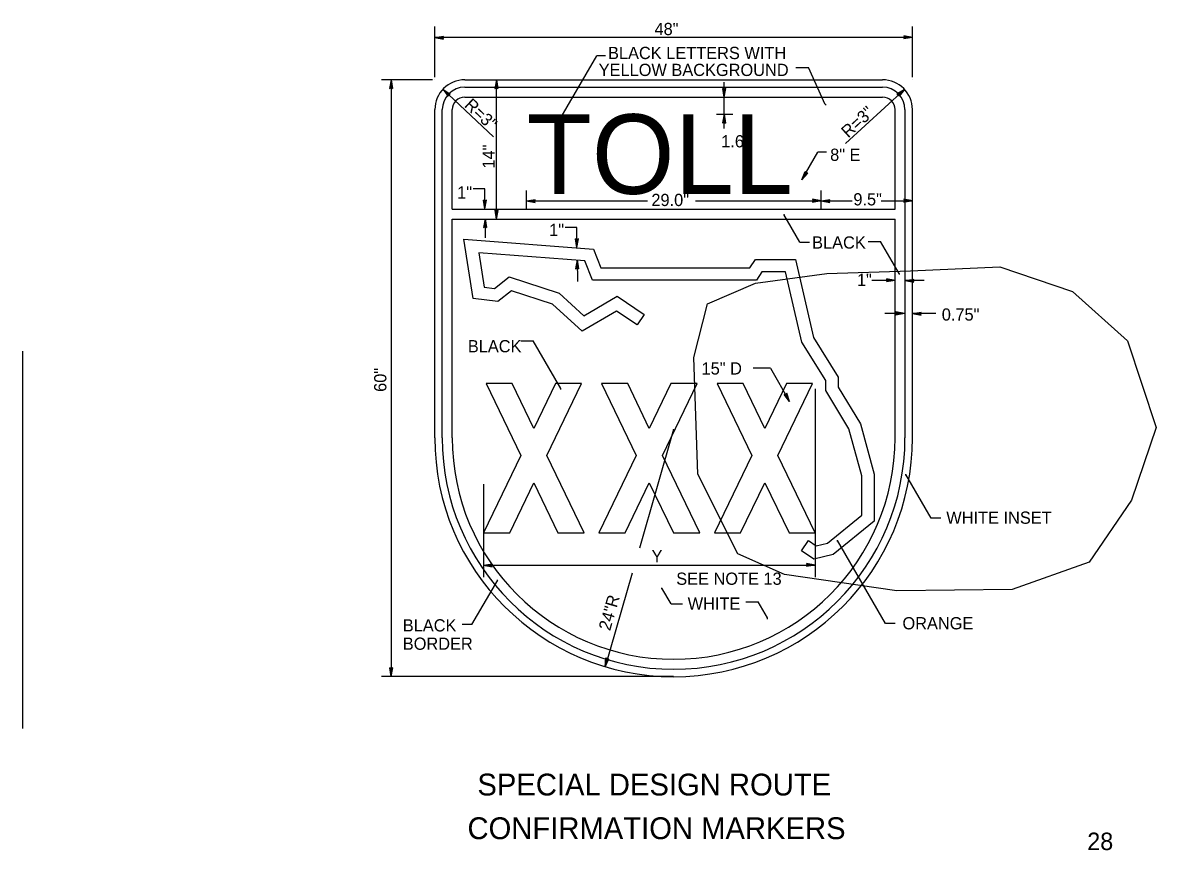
# Model space of a CAD drawing. Extents: x 51788 to 52424, y 9835 to 10249.
# Drawn here: x 52164.7 to 52424.2, y 9845.3 to 10034.8 of the extents above; entities that cross this region are included whole.
import ezdxf

# ---------------------------------------------------------------- set-up
doc = ezdxf.new("R2010")
doc.units = 0
for name, color, linetype in [('DimLines_dp', 7, 'Continuous'), ('GSColorFill', 7, 'Continuous'), ('GSDims', 7, 'Continuous'), ('SignPanel', 7, 'Continuous'), ('TextAlert', 7, 'Continuous'), ('TextMisc', 7, 'Continuous'), ('TextShtNo', 7, 'Continuous')]:
    doc.layers.add(name, color=color, linetype=linetype)

msp = doc.modelspace()

# ---------------------------------------------------------------- linework, layer by layer
at = {"layer": 'DimLines_dp'}
msp.add_line((52313.7, 9941.63), (52313.7, 9941.63), dxfattribs=at)
msp.add_line((52313.7, 9941.63), (52313.7, 9941.63), dxfattribs=at)
for radius in [0.0387, 0.0387, 0.0193]:
    msp.add_circle((52313.7, 9941.63), radius, dxfattribs=at)
at = {"layer": 'GSColorFill'}
for p, q in [((52270.76, 9952.16), (52278.69, 9935.69)), ((52276.75, 9952.16), (52270.76, 9952.16)), ((52270.76, 9952.16), (52278.69, 9935.69)), ((52276.75, 9952.16), (52270.76, 9952.16)), ((52281.69, 9941.91), (52276.75, 9952.16)), ((52281.69, 9941.91), (52276.75, 9952.16)), ((52286.63, 9952.16), (52281.69, 9941.91)), ((52286.63, 9952.16), (52281.69, 9941.91)), ((52284.69, 9935.69), (52292.63, 9952.16)), ((52284.69, 9935.69), (52292.63, 9952.16)), ((52292.63, 9952.16), (52286.63, 9952.16)), ((52292.63, 9952.16), (52286.63, 9952.16)), ((52297.2, 9952.16), (52305.13, 9935.69)), ((52303.19, 9952.16), (52297.2, 9952.16)), ((52297.2, 9952.16), (52305.13, 9935.69)), ((52303.19, 9952.16), (52297.2, 9952.16)), ((52308.13, 9941.91), (52303.19, 9952.16)), ((52308.13, 9941.91), (52303.19, 9952.16)), ((52313.07, 9952.16), (52308.13, 9941.91)), ((52313.07, 9952.16), (52308.13, 9941.91)), ((52311.13, 9935.69), (52319.07, 9952.16)), ((52311.13, 9935.69), (52319.07, 9952.16)), ((52319.07, 9952.16), (52313.07, 9952.16)), ((52319.07, 9952.16), (52313.07, 9952.16)), ((52323.64, 9952.16), (52331.58, 9935.69)), ((52329.63, 9952.16), (52323.64, 9952.16)), ((52323.64, 9952.16), (52331.58, 9935.69)), ((52329.63, 9952.16), (52323.64, 9952.16)), ((52334.57, 9941.91), (52329.63, 9952.16)), ((52334.57, 9941.91), (52329.63, 9952.16)), ((52339.51, 9952.16), (52334.57, 9941.91)), ((52339.51, 9952.16), (52334.57, 9941.91)), ((52337.57, 9935.69), (52345.51, 9952.16)), ((52337.57, 9935.69), (52345.51, 9952.16)), ((52345.51, 9952.16), (52339.51, 9952.16)), ((52345.51, 9952.16), (52339.51, 9952.16)), ((52278.69, 9935.69), (52270.16, 9917.99)), ((52278.69, 9935.69), (52270.16, 9917.99)), ((52293.22, 9917.99), (52284.69, 9935.69)), ((52293.22, 9917.99), (52284.69, 9935.69)), ((52305.13, 9935.69), (52296.6, 9917.99)), ((52305.13, 9935.69), (52296.6, 9917.99)), ((52319.66, 9917.99), (52311.13, 9935.69)), ((52319.66, 9917.99), (52311.13, 9935.69)), ((52331.58, 9935.69), (52323.05, 9917.99)), ((52331.58, 9935.69), (52323.05, 9917.99)), ((52346.1, 9917.99), (52337.57, 9935.69)), ((52346.1, 9917.99), (52337.57, 9935.69)), ((52276.16, 9917.99), (52281.69, 9929.47)), ((52276.16, 9917.99), (52281.69, 9929.47)), ((52281.69, 9929.47), (52287.22, 9917.99)), ((52281.69, 9929.47), (52287.22, 9917.99)), ((52302.6, 9917.99), (52308.13, 9929.47)), ((52302.6, 9917.99), (52308.13, 9929.47)), ((52308.13, 9929.47), (52313.67, 9917.99)), ((52308.13, 9929.47), (52313.67, 9917.99)), ((52329.04, 9917.99), (52334.57, 9929.47)), ((52329.04, 9917.99), (52334.57, 9929.47)), ((52334.57, 9929.47), (52340.11, 9917.99)), ((52334.57, 9929.47), (52340.11, 9917.99)), ((52270.16, 9917.99), (52276.16, 9917.99)), ((52270.16, 9917.99), (52276.16, 9917.99)), ((52287.22, 9917.99), (52293.22, 9917.99)), ((52287.22, 9917.99), (52293.22, 9917.99)), ((52296.6, 9917.99), (52302.6, 9917.99)), ((52296.6, 9917.99), (52302.6, 9917.99)), ((52313.67, 9917.99), (52319.66, 9917.99)), ((52313.67, 9917.99), (52319.66, 9917.99)), ((52323.05, 9917.99), (52329.04, 9917.99)), ((52323.05, 9917.99), (52329.04, 9917.99)), ((52340.11, 9917.99), (52346.1, 9917.99)), ((52340.11, 9917.99), (52346.1, 9917.99))]:
    msp.add_line(p, q, dxfattribs=at)
for points in [[(52270.76, 9952.16), (52278.69, 9935.69), (52270.16, 9917.99), (52276.16, 9917.99), (52281.69, 9929.47), (52287.22, 9917.99), (52293.22, 9917.99), (52284.69, 9935.69), (52292.63, 9952.16), (52286.63, 9952.16), (52281.69, 9941.91), (52276.75, 9952.16)], [(52297.2, 9952.16), (52305.13, 9935.69), (52296.6, 9917.99), (52302.6, 9917.99), (52308.13, 9929.47), (52313.67, 9917.99), (52319.66, 9917.99), (52311.13, 9935.69), (52319.07, 9952.16), (52313.07, 9952.16), (52308.13, 9941.91), (52303.19, 9952.16)], [(52323.64, 9952.16), (52331.58, 9935.69), (52323.05, 9917.99), (52329.04, 9917.99), (52334.57, 9929.47), (52340.11, 9917.99), (52346.1, 9917.99), (52337.57, 9935.69), (52345.51, 9952.16), (52339.51, 9952.16), (52334.57, 9941.91), (52329.63, 9952.16)]]:
    msp.add_lwpolyline(points, close=True, dxfattribs=at)
at = {"layer": 'GSDims'}
for p, q in [((52259.03, 10022.32), (52259.03, 10033.96)), ((52368.39, 10022.32), (52368.39, 10033.96)), ((52259.03, 10031.43), (52261.03, 10031.75)), ((52259.03, 10031.43), (52260.95, 10031.57)), ((52259.03, 10031.43), (52261.02, 10031.05)), ((52259.03, 10031.43), (52260.95, 10031.23)), ((52368.39, 10031.43), (52259.03, 10031.43)), ((52260.88, 10031.41), (52261.03, 10031.75)), ((52261.02, 10031.05), (52260.88, 10031.41)), ((52366.54, 10031.46), (52366.39, 10031.12)), ((52368.39, 10031.43), (52366.39, 10031.12)), ((52368.39, 10031.43), (52366.4, 10031.82)), ((52366.4, 10031.82), (52366.54, 10031.46)), ((52368.39, 10031.43), (52366.47, 10031.64)), ((52368.39, 10031.43), (52366.47, 10031.3)), ((52286.9, 10011.34), (52296.1, 10027.25)), ((52298.07, 10027.25), (52296.1, 10027.25)), ((52341.7, 10024.55), (52344.56, 10024.55)), ((52348.37, 10016.08), (52344.56, 10024.55)), ((52258.47, 10021.76), (52246.83, 10021.76)), ((52249.04, 10021.76), (52248.66, 10019.77)), ((52249.04, 10021.76), (52248.84, 10019.84)), ((52249.04, 10021.76), (52249.36, 10019.76)), ((52249.04, 10021.76), (52249.18, 10019.84)), ((52249.04, 10021.76), (52249.04, 9885.07)), ((52259.03, 10021.76), (52259.03, 10021.76)), ((52273.15, 10021.76), (52272.77, 10019.77)), ((52273.15, 10021.76), (52272.95, 10019.84)), ((52273.15, 10021.76), (52273.47, 10019.76)), ((52273.15, 10021.76), (52273.29, 10019.84)), ((52273.15, 9989.85), (52273.15, 10021.76)), ((52325.29, 10017.77), (52325.29, 10021.21)), ((52368.39, 10021.76), (52368.39, 10021.76)), ((52248.66, 10019.77), (52249.01, 10019.91)), ((52249.01, 10019.91), (52249.36, 10019.76)), ((52260.89, 10019.6), (52262.56, 10018.46)), ((52260.89, 10019.6), (52262.07, 10017.96)), ((52260.89, 10019.6), (52262.15, 10018.15)), ((52260.89, 10019.6), (52262.38, 10018.38)), ((52260.89, 10019.6), (52272.48, 10008.67)), ((52262.07, 10017.96), (52262.2, 10018.31)), ((52262.2, 10018.31), (52262.56, 10018.46)), ((52272.77, 10019.77), (52273.13, 10019.91)), ((52273.13, 10019.91), (52273.47, 10019.76)), ((52325.29, 10017.77), (52324.97, 10019.76)), ((52325.31, 10019.61), (52324.97, 10019.76)), ((52325.29, 10017.77), (52325.15, 10019.68)), ((52325.29, 10017.77), (52325.67, 10019.75)), ((52325.29, 10017.77), (52325.49, 10019.68)), ((52325.67, 10019.75), (52325.31, 10019.61)), ((52366.55, 10019.54), (52353.05, 10007.11)), ((52366.55, 10019.54), (52364.83, 10018.48)), ((52364.83, 10018.48), (52365.17, 10018.31)), ((52366.55, 10019.54), (52365.01, 10018.39)), ((52365.17, 10018.31), (52365.3, 10017.96)), ((52366.55, 10019.54), (52365.24, 10018.15)), ((52366.55, 10019.54), (52365.3, 10017.96)), ((52325.29, 10013.83), (52325.29, 10017.77)), ((52323.48, 10013.83), (52327.21, 10013.83)), ((52325.29, 10013.83), (52324.9, 10011.85)), ((52325.29, 10013.83), (52325.08, 10011.92)), ((52325.29, 10010.55), (52325.29, 10013.83)), ((52325.29, 10013.83), (52325.6, 10011.83)), ((52325.29, 10013.83), (52325.42, 10011.92)), ((52324.9, 10011.85), (52325.26, 10011.98)), ((52325.26, 10011.98), (52325.6, 10011.83)), ((52343.07, 9998.82), (52346.73, 10005.16)), ((52348.7, 10005.16), (52346.73, 10005.16)), ((52343.07, 9998.82), (52343.8, 10000.71)), ((52343.07, 9998.82), (52343.92, 10000.54)), ((52343.07, 9998.82), (52344.21, 10000.38)), ((52343.07, 9998.82), (52344.4, 10000.35)), ((52344.01, 10000.39), (52343.8, 10000.71)), ((52344.4, 10000.35), (52344.01, 10000.39)), ((52270.46, 9996.78), (52267.8, 9996.78)), ((52270.5, 9992.15), (52270.46, 9996.78)), ((52280, 9992.12), (52280, 9996.39)), ((52347.45, 9992.12), (52347.45, 9996.39)), ((52270.5, 9992.15), (52270.16, 9994.15)), ((52270.52, 9993.99), (52270.16, 9994.15)), ((52270.5, 9992.15), (52270.35, 9994.06)), ((52270.5, 9992.15), (52270.87, 9994.15)), ((52270.5, 9992.15), (52270.68, 9994.06)), ((52270.87, 9994.15), (52270.52, 9993.99)), ((52280, 9993.98), (52282, 9994.3)), ((52280, 9993.98), (52281.92, 9994.12)), ((52280, 9993.98), (52281.98, 9993.6)), ((52280, 9993.98), (52281.92, 9993.78)), ((52280, 9993.98), (52307.7, 9993.98)), ((52281.85, 9993.95), (52282, 9994.3)), ((52281.98, 9993.6), (52281.85, 9993.95)), ((52318.68, 9993.98), (52347.45, 9993.98)), ((52345.6, 9994.01), (52345.45, 9993.67)), ((52347.45, 9993.98), (52345.45, 9993.67)), ((52347.45, 9993.98), (52345.46, 9994.36)), ((52345.46, 9994.36), (52345.6, 9994.01)), ((52347.45, 9993.98), (52345.53, 9994.19)), ((52347.45, 9993.98), (52345.53, 9993.84)), ((52347.45, 9993.98), (52349.44, 9994.3)), ((52347.45, 9993.98), (52349.36, 9994.12)), ((52347.45, 9993.98), (52349.43, 9993.6)), ((52347.45, 9993.98), (52349.36, 9993.78)), ((52347.45, 9993.98), (52354.57, 9993.98)), ((52349.29, 9993.95), (52349.44, 9994.3)), ((52349.43, 9993.6), (52349.29, 9993.95)), ((52361.22, 9993.98), (52368.39, 9993.98)), ((52366.54, 9994.01), (52366.39, 9993.67)), ((52368.39, 9993.98), (52366.39, 9993.67)), ((52368.39, 9993.98), (52366.4, 9994.36)), ((52366.4, 9994.36), (52366.54, 9994.01)), ((52368.39, 9993.98), (52366.47, 9994.19)), ((52368.39, 9993.98), (52366.47, 9993.84)), ((52270.53, 9989.88), (52270.16, 9987.88)), ((52270.53, 9989.88), (52270.35, 9987.97)), ((52270.53, 9989.88), (52270.87, 9987.88)), ((52270.53, 9989.88), (52270.68, 9987.97)), ((52270.53, 9989.88), (52270.58, 9985.56)), ((52273.15, 9989.85), (52272.84, 9991.85)), ((52273.18, 9991.7), (52272.84, 9991.85)), ((52273.15, 9989.85), (52273.02, 9991.77)), ((52273.15, 9989.85), (52273.54, 9991.84)), ((52273.15, 9989.85), (52273.36, 9991.77)), ((52273.54, 9991.84), (52273.18, 9991.7)), ((52342.57, 9984.58), (52338.9, 9990.92)), ((52270.16, 9987.88), (52270.52, 9988.04)), ((52270.52, 9988.04), (52270.87, 9987.88)), ((52291.53, 9987.93), (52288.86, 9987.93)), ((52291.57, 9983.3), (52291.53, 9987.93)), ((52291.57, 9983.3), (52291.23, 9985.29)), ((52291.58, 9985.14), (52291.23, 9985.29)), ((52291.57, 9983.3), (52291.42, 9985.21)), ((52291.57, 9983.3), (52291.94, 9985.29)), ((52291.57, 9983.3), (52291.75, 9985.21)), ((52291.94, 9985.29), (52291.58, 9985.14)), ((52342.57, 9984.58), (52344.8, 9984.58)), ((52358.22, 9984.67), (52361.07, 9984.67)), ((52365.31, 9977.35), (52361.07, 9984.67)), ((52291.6, 9980.48), (52291.23, 9978.48)), ((52291.6, 9980.48), (52291.42, 9978.56)), ((52291.6, 9980.48), (52291.94, 9978.48)), ((52291.6, 9980.48), (52291.75, 9978.56)), ((52291.6, 9980.48), (52291.65, 9975.54)), ((52291.23, 9978.48), (52291.58, 9978.63)), ((52291.58, 9978.63), (52291.94, 9978.48)), ((52364.42, 9975.79), (52359.08, 9975.79)), ((52362.58, 9975.81), (52362.43, 9975.47)), ((52364.42, 9975.79), (52362.43, 9975.47)), ((52364.42, 9975.79), (52362.44, 9976.17)), ((52362.44, 9976.17), (52362.58, 9975.81)), ((52364.42, 9975.79), (52362.51, 9975.99)), ((52364.42, 9975.79), (52362.51, 9975.65)), ((52366.69, 9975.79), (52368.69, 9976.1)), ((52366.69, 9975.79), (52368.6, 9975.92)), ((52366.69, 9975.79), (52368.67, 9975.4)), ((52366.69, 9975.79), (52368.6, 9975.58)), ((52371.07, 9975.79), (52366.69, 9975.79)), ((52368.54, 9975.76), (52368.69, 9976.1)), ((52368.67, 9975.4), (52368.54, 9975.76)), ((52366.57, 9968.19), (52364.59, 9968.57)), ((52364.59, 9968.57), (52364.72, 9968.21)), ((52366.57, 9968.19), (52362.06, 9968.19)), ((52364.72, 9968.21), (52364.57, 9967.87)), ((52366.57, 9968.19), (52364.57, 9967.87)), ((52366.57, 9968.19), (52364.65, 9968.39)), ((52366.57, 9968.19), (52364.65, 9968.05)), ((52368.39, 9968.19), (52370.38, 9968.5)), ((52368.39, 9968.19), (52370.3, 9968.32)), ((52368.39, 9968.19), (52370.37, 9967.8)), ((52368.39, 9968.19), (52370.3, 9967.98)), ((52373.73, 9968.19), (52368.39, 9968.19)), ((52370.23, 9968.16), (52370.38, 9968.5)), ((52370.37, 9967.8), (52370.23, 9968.16)), ((52278.69, 9961.99), (52281.55, 9961.99)), ((52287.87, 9951.07), (52281.55, 9961.99)), ((52335.87, 9955.67), (52331.87, 9955.67)), ((52335.87, 9955.67), (52340.24, 9948.09)), ((52346.1, 9950.96), (52346.1, 9907.82)), ((52339.35, 9949.69), (52338.97, 9949.66)), ((52340.24, 9948.09), (52338.97, 9949.66)), ((52340.24, 9948.09), (52339.17, 9949.69)), ((52339.58, 9950), (52339.35, 9949.69)), ((52340.24, 9948.09), (52339.46, 9949.85)), ((52340.24, 9948.09), (52339.58, 9950)), ((52313.7, 9941.63), (52305.87, 9914.51)), ((52372.66, 9921.34), (52366.88, 9931.36)), ((52270.16, 9929.11), (52270.16, 9907.82)), ((52374.87, 9921.34), (52372.66, 9921.34)), ((52362.19, 9897.23), (52351.22, 9916.21)), ((52270.16, 9910.58), (52272.16, 9910.9)), ((52270.16, 9910.58), (52272.08, 9910.72)), ((52270.16, 9910.58), (52272.15, 9910.2)), ((52270.16, 9910.58), (52272.08, 9910.38)), ((52270.16, 9910.58), (52346.1, 9910.58)), ((52272.01, 9910.56), (52272.16, 9910.9)), ((52272.15, 9910.2), (52272.01, 9910.56)), ((52344.26, 9910.61), (52344.11, 9910.27)), ((52346.1, 9910.58), (52344.11, 9910.27)), ((52346.1, 9910.58), (52344.12, 9910.97)), ((52344.12, 9910.97), (52344.26, 9910.61)), ((52346.1, 9910.58), (52344.19, 9910.79)), ((52346.1, 9910.58), (52344.19, 9910.45)), ((52267.52, 9896.97), (52273.41, 9907.16)), ((52304.21, 9908.76), (52298.03, 9887.34)), ((52313.1, 9901.77), (52311.02, 9905.36)), ((52313.1, 9901.77), (52315.7, 9901.77)), ((52330.21, 9902.19), (52333.07, 9902.19)), ((52335.2, 9898.5), (52333.07, 9902.19)), ((52267.52, 9896.97), (52265.32, 9896.97)), ((52364.39, 9897.23), (52362.19, 9897.23)), ((52298.03, 9887.34), (52298.21, 9889.35)), ((52298.03, 9887.34), (52298.37, 9889.24)), ((52298.03, 9887.34), (52298.89, 9889.17)), ((52298.03, 9887.34), (52298.7, 9889.15)), ((52298.21, 9889.35), (52298.52, 9889.12)), ((52298.52, 9889.12), (52298.89, 9889.17)), ((52249.04, 9885.07), (52248.73, 9887.06)), ((52249.07, 9886.91), (52248.73, 9887.06)), ((52249.04, 9885.07), (52248.9, 9886.98)), ((52249.04, 9885.07), (52249.42, 9887.05)), ((52249.04, 9885.07), (52249.25, 9886.98)), ((52249.42, 9887.05), (52249.07, 9886.91)), ((52313.68, 9885.07), (52246.83, 9885.07)), ((52259.03, 9885.04), (52259.03, 9885.04))]:
    msp.add_line(p, q, dxfattribs=at)
msp.add_lwpolyline([(52321.45, 9970.42), (52332.45, 9975.14), (52348.79, 9977.34), (52367.95, 9977.97), (52388.38, 9978.91), (52405.03, 9973.25), (52417.6, 9961.93), (52424.2, 9942.12), (52418.54, 9925.45), (52408.8, 9911.3), (52391.21, 9905.01), (52364.81, 9904.7), (52339.05, 9908.47), (52328.36, 9913.19), (52319.25, 9931.43), (52318.31, 9958.16), (52321.45, 9970.42)], dxfattribs=at)
at = {"layer": 'SignPanel'}
for p, q in [((52265.87, 10021.76), (52361.52, 10021.76)), ((52265.87, 10020.03), (52361.52, 10020.03)), ((52265.87, 10017.77), (52361.52, 10017.77)), ((52259.01, 9939.71), (52259.03, 10014.92)), ((52260.7, 9939.71), (52260.73, 10014.92)), ((52263, 9992.12), (52263, 10014.92)), ((52364.42, 9992.12), (52364.42, 10014.92)), ((52366.69, 9939.71), (52366.69, 10014.92)), ((52368.39, 9939.71), (52368.39, 10014.92)), ((52263, 9992.12), (52277.27, 9992.12)), ((52277.27, 9992.12), (52364.42, 9992.12)), ((52262.97, 9939.71), (52263, 9989.85)), ((52263, 9989.85), (52364.42, 9989.85)), ((52364.42, 9939.71), (52364.42, 9989.85)), ((52267.8, 9971.68), (52265.68, 9985.27)), ((52265.68, 9985.27), (52295.38, 9982.98)), ((52293.37, 9980.26), (52269.07, 9982.14)), ((52269.07, 9982.14), (52270.29, 9974.26)), ((52295.38, 9982.98), (52297.05, 9978.71)), ((52295.09, 9975.84), (52293.37, 9980.26)), ((52331.12, 9978.71), (52332.4, 9980.6)), ((52332.4, 9980.6), (52341.57, 9980.6)), ((52341.57, 9980.6), (52345.72, 9962.75)), ((52272.65, 9973.97), (52276.02, 9976.63)), ((52276.02, 9976.63), (52287.48, 9972.9)), ((52297.05, 9978.71), (52331.12, 9978.71)), ((52333.92, 9977.74), (52332.64, 9975.84)), ((52339.29, 9977.74), (52333.92, 9977.74)), ((52343.03, 9961.64), (52339.29, 9977.74)), ((52270.29, 9974.26), (52272.65, 9973.97)), ((52332.64, 9975.84), (52295.09, 9975.84)), ((52273.48, 9970.98), (52267.8, 9971.68)), ((52276.59, 9973.43), (52273.48, 9970.98)), ((52286, 9970.37), (52276.59, 9973.43)), ((52287.48, 9972.9), (52293.11, 9967.69)), ((52293.11, 9967.69), (52300.73, 9972.17)), ((52300.73, 9972.17), (52306.94, 9967.97)), ((52292.72, 9964.14), (52286, 9970.37)), ((52300.63, 9968.78), (52292.72, 9964.14)), ((52305.33, 9965.6), (52300.63, 9968.78)), ((52306.94, 9967.97), (52305.33, 9965.6)), ((52348.5, 9952.85), (52343.03, 9961.64)), ((52345.72, 9962.75), (52351.36, 9953.67)), ((52351.36, 9953.67), (52351.36, 9951.38)), ((52348.5, 9950.58), (52348.5, 9952.85)), ((52353.82, 9941.82), (52348.5, 9950.58)), ((52351.36, 9951.38), (52356.48, 9942.96)), ((52356.48, 9942.96), (52359.62, 9931.45)), ((52356.76, 9931.07), (52353.82, 9941.82)), ((52356.76, 9922.05), (52356.76, 9931.07)), ((52359.62, 9931.45), (52359.62, 9920.69)), ((52348.93, 9915.64), (52356.76, 9922.05)), ((52359.62, 9920.69), (52350.24, 9913)), ((52342.96, 9913.9), (52344.59, 9916.25)), ((52344.59, 9916.25), (52346.36, 9915.02)), ((52346.36, 9915.02), (52348.93, 9915.64)), ((52345.78, 9911.94), (52342.96, 9913.9)), ((52350.24, 9913), (52345.78, 9911.94))]:
    msp.add_line(p, q, dxfattribs=at)
for centre, radius, start, end in [((52265.87, 10014.91), 6.83, 90, 179.9792), ((52361.53, 10014.91), 6.83, 0, 90), ((52265.87, 10014.91), 5.13, 90, 179.9792), ((52361.53, 10014.91), 5.13, 0, 90), ((52265.87, 10014.91), 2.85, 90, 179.9792), ((52361.53, 10014.91), 2.85, 0, 90), ((52313.69, 9939.73), 54.68, 180, 0), ((52313.69, 9939.73), 52.97, 180, 0), ((52313.69, 9939.73), 50.69, 180, 0)]:
    msp.add_arc(centre, radius, start, end, dxfattribs=at)
at = {"layer": 'TextAlert'}
msp.add_line((52164.67, 9873.2), (52164.67, 9959.57), dxfattribs=at)

# ---------------------------------------------------------------- texts
at = {"layer": 'DimLines_dp'}
msp.add_text('.', height=2.3, rotation=90, dxfattribs=at).set_placement((52313.98, 9941.13))
at = {"layer": 'GSDims'}
for s, height, p in [('48"', 2.8, (52309.32, 10031.97)), ('BLACK LETTERS WITH', 2.8, (52298.68, 10026.48)), ('YELLOW BACKGROUND', 2.8, (52296.54, 10022.6)), ('.', 2.3, (52286.58, 10011.03)), ('1.6"', 2.8, (52324.59, 10006.26)), ('8" E ', 2.8, (52349.53, 10003.17)), ('1"', 2.8, (52264.13, 9994.54)), ('29.0"', 2.8, (52308.6, 9992.82)), ('9.5"', 2.8, (52354.84, 9992.97)), ('1"', 2.8, (52285.2, 9985.96)), ('BLACK', 2.8, (52345.4, 9983.08)), ('1"', 2.8, (52355.66, 9974.51)), ('0.75"', 2.8, (52375.08, 9966.59)), ('BLACK', 2.8, (52266.58, 9959.33)), ('15" D', 2.8, (52320.09, 9954.24)), ('.', 2.3, (52287.4, 9950.79)), ('WHITE INSET', 2.8, (52376.11, 9920.07)), ('.', 2.3, (52350.73, 9915.96)), ('Y', 2.8, (52308.64, 9911.26)), ('SEE NOTE 13', 2.8, (52314.29, 9906.09)), ('.', 2.3, (52272.92, 9906.92)), ('.', 2.3, (52310.54, 9905.1)), ('WHITE', 2.8, (52316.91, 9900.39)), ('.', 2.3, (52334.7, 9898.22)), ('ORANGE', 2.8, (52366.08, 9895.89)), ('BLACK', 2.8, (52251.69, 9895.41)), ('BORDER', 2.8, (52251.69, 9891.21))]:
    msp.add_text(s, height=height, dxfattribs=at).set_placement(p)
for s, height, rotation, p in [('R=3"', 2.8, 316.6507, (52265.61, 10015.71)), ('.', 2.3, 90, (52348.67, 10015.58)), ('R=3"', 2.8, 42.6037, (52353.65, 10008.28)), ('14"', 2.8, 90, (52272.74, 10001.4)), ('.', 1.97, 90, (52365.55, 9976.9)), ('60"', 2.8, 90, (52247.93, 9950.27)), ('24"R', 2.8, 73.9233, (52299.14, 9895.41))]:
    msp.add_text(s, height=height, rotation=rotation, dxfattribs=at).set_placement(p)
at = {"layer": 'SignPanel'}
for s, height, p in [('TOLL', 18.221, (52280.07, 9995.61)), ('.', 2.3, (52366.4, 9931.09))]:
    msp.add_text(s, height=height, dxfattribs=at).set_placement(p)
msp.add_text('.', height=2.3, rotation=90, dxfattribs=at).set_placement((52339.18, 9990.38))
at = {"layer": 'TextMisc'}
for s, p in [('  SPECIAL DESIGN ROUTE  ', (52265.05, 9857.85)), ('  CONFIRMATION MARKERS  ', (52262.79, 9847.85))]:
    msp.add_text(s, height=5, rotation=360, dxfattribs=at).set_placement(p)
at = {"layer": 'TextShtNo'}
msp.add_text('28', height=4, rotation=360, dxfattribs=at).set_placement((52408.38, 9845.35))

doc.saveas('drawing.dxf')
